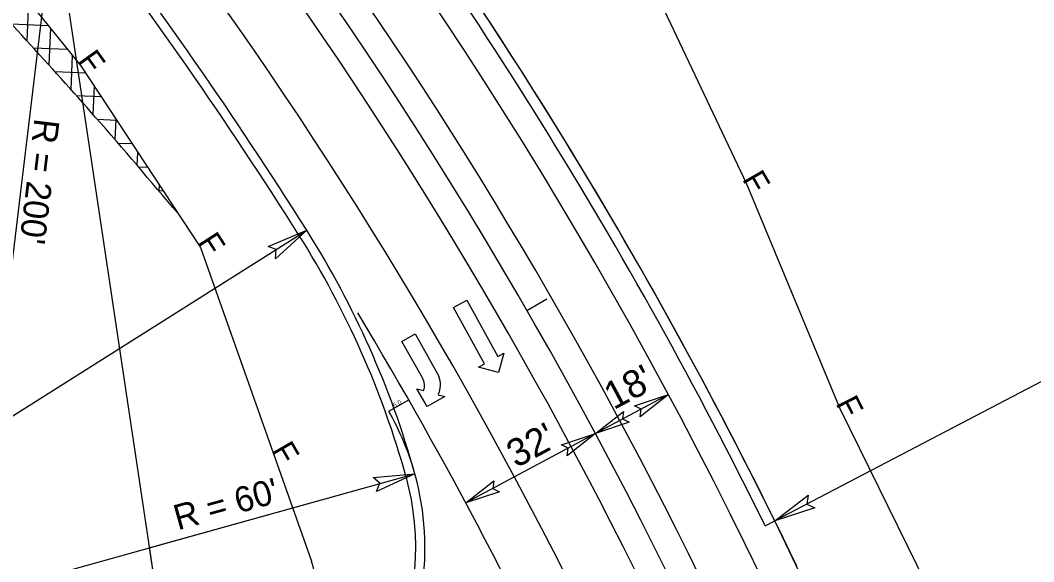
# Model space of a CAD drawing. Extents: x 1702862 to 1704514, y 793768 to 796215.
# Drawn here: x 1703745.4 to 1703965.8, y 794569.2 to 794687 of the extents above; entities that cross this region are included whole.
import ezdxf

# ---------------------------------------------------------------- set-up
doc = ezdxf.new("R2010")
doc.units = 0
for name, color, linetype in [('Prop Conc 2ft 6in Curb and Gutter', 7, 'Continuous'), ('Prop Conc Shoulder Berm Gutter', 7, 'Continuous'), ('Prop Dimension', 7, 'Continuous'), ('Prop Dimension Text', 7, 'Continuous'), ('Prop EOT', 7, 'Continuous'), ('Prop Guardrail', 7, 'Continuous'), ('Prop Horizontal Alignment', 7, 'Continuous'), ('Prop Horizontal Alignment Tick Small', 7, 'Continuous'), ('Prop Lane Arrow CELL', 7, 'Continuous'), ('Prop Lane Lines', 7, 'Continuous'), ('Prop Leader Line Medium', 7, 'Continuous'), ('Prop Paved Shoulder', 7, 'Continuous'), ('Prop Rem of Exist Asph Pvmt', 7, 'Continuous'), ('Prop SS Fill Line', 7, 'Continuous'), ('Prop SS Misc', 7, 'Continuous'), ('Prop SS Transition Line', 7, 'Continuous'), ('Prop Terminator CELL', 7, 'Continuous')]:
    doc.layers.add(name, color=color, linetype=linetype)

msp = doc.modelspace()

# ---------------------------------------------------------------- linework, layer by layer
at = {"layer": 'Prop Conc 2ft 6in Curb and Gutter'}
for centre, radius, start, end in [((1702985.28, 794122.36), 970.46, 32.25438, 42.65517), ((1703638.54, 794534.6), 198, 15.5759, 32.2542), ((1703773.4, 794572.2), 58, 295.8355, 15.5759)]:
    msp.add_arc(centre, radius, start, end, dxfattribs=at)
at = {"layer": 'Prop Conc Shoulder Berm Gutter'}
msp.add_arc((1702988.97, 794124.56), 1026.16, 26.22656, 37.4674, dxfattribs=at)
at = {"layer": 'Prop Dimension'}
for p, q in [((1703752.73, 794710.66), (1703728.81, 794512.1)), ((1703752.73, 794710.66), (1703782.26, 794512.85)), ((1703638.54, 794534.6), (1703807.68, 794641.34)), ((1703825.51, 794601.94), (1703829.85, 794604.42)), ((1703886.34, 794605.58), (1703870.48, 794597.08)), ((1703870.48, 794597.08), (1703842.27, 794581.96)), ((1703638.54, 794534.6), (1703831.2, 794588.31)), ((1703773.4, 794572.2), (1703831.2, 794588.31)), ((1703773.4, 794572.2), (1703782.26, 794512.85))]:
    msp.add_line(p, q, dxfattribs=at)
msp.add_arc((1703773.4, 794572.2), 60, 15.5759, 29.7174, dxfattribs=at)
at = {"layer": 'Prop EOT'}
for centre, radius, start, end in [((1702989.11, 794124.65), 1018, 14.75888, 42.70907), ((1702985.01, 794122.19), 972.78, 32.25419, 42.65174), ((1703638.54, 794534.6), 200, 15.5759, 32.2542), ((1703773.4, 794572.2), 60, 278.4921, 15.5759)]:
    msp.add_arc(centre, radius, start, end, dxfattribs=at)
at = {"layer": 'Prop Guardrail'}
msp.add_arc((1702988.97, 794124.56), 1026.16, 25.61718, 37.4674, dxfattribs=at)
at = {"layer": 'Prop Horizontal Alignment'}
msp.add_arc((1702989.11, 794124.65), 1000, 351.25916, 42.70907, dxfattribs=at)
at = {"layer": 'Prop Horizontal Alignment Tick Small'}
msp.add_line((1703855.57, 794623.89), (1703859.9, 794626.39), dxfattribs=at)
at = {"layer": 'Prop Lane Arrow CELL'}
for p, q in [((1703839.59, 794624.51), (1703842.48, 794626.11)), ((1703846.38, 794612.27), (1703839.59, 794624.51)), ((1703842.48, 794626.11), (1703849.27, 794613.87)), ((1703828.35, 794617.15), (1703831.23, 794618.77)), ((1703831.23, 794618.77), (1703836.41, 794609.58)), ((1703832.85, 794609.18), (1703828.35, 794617.15)), ((1703849.27, 794613.87), (1703850.58, 794614.59)), ((1703850.58, 794614.59), (1703849.39, 794610.33)), ((1703845.07, 794611.54), (1703846.38, 794612.27)), ((1703849.39, 794610.33), (1703845.07, 794611.54)), ((1703833.9, 794602.94), (1703831.65, 794606.83)), ((1703831.65, 794606.83), (1703833.08, 794606.44)), ((1703837.71, 794605.15), (1703833.9, 794602.94)), ((1703836.28, 794605.54), (1703837.71, 794605.15))]:
    msp.add_line(p, q, dxfattribs=at)
for centre, radius, start, end in [((1703830.02, 794607.57), 3.28, 339.7935, 29.4516), ((1703831.52, 794607.73), 5.25, 335.4639, 20.7756)]:
    msp.add_arc(centre, radius, start, end, dxfattribs=at)
at = {"layer": 'Prop Lane Lines'}
for radius, start, end in [(1006, 0.00687, 42.70907), (994, 359.40932, 42.70907), (980, 359.40932, 42.70907), (968, 17.6382, 31.00789)]:
    msp.add_arc((1702989.11, 794124.65), radius, start, end, dxfattribs=at)
at = {"layer": 'Prop Leader Line Medium'}
msp.add_line((1704040.99, 794646.92), (1703909.49, 794578.04), dxfattribs=at)
at = {"layer": 'Prop Paved Shoulder'}
for p in [(1703907.4, 794577.02), (1703914.93, 794566.65)]:
    msp.add_line(p, (1703909.49, 794578.04), dxfattribs=at)
msp.add_arc((1702988.97, 794124.56), 1023.83, 26.22656, 37.4674, dxfattribs=at)
at = {"layer": 'Prop Rem of Exist Asph Pvmt'}
for p, q in [((1703747.15, 794691.23), (1703746.8, 794682.65)), ((1703743.47, 794686.26), (1703751.41, 794685.94)), ((1703751.91, 794685.31), (1703751.6, 794677.4)), ((1703748.26, 794681.06), (1703755.57, 794680.77)), ((1703756.68, 794679.38), (1703756.39, 794672.06)), ((1703752.98, 794675.87), (1703759.5, 794675.61)), ((1703757.61, 794670.68), (1703762.88, 794670.47)), ((1703761.42, 794672.69), (1703761.17, 794666.58)), ((1703762.1, 794665.49), (1703766.27, 794665.33)), ((1703766.14, 794665.53), (1703765.95, 794661)), ((1703766.54, 794660.31), (1703769.65, 794660.19)), ((1703770.85, 794658.36), (1703770.73, 794655.41)), ((1703770.97, 794655.13), (1703773.04, 794655.05)), ((1703775.57, 794651.2), (1703775.52, 794649.83)), ((1703775.41, 794649.95), (1703776.42, 794649.91))]:
    msp.add_line(p, q, dxfattribs=at)
msp.add_spline([(1703779.68, 794644.96), (1703761.75, 794665.91), (1703731.32, 794699.4), (1703700.82, 794732.47), (1703669.4, 794765.36)], degree=3, dxfattribs=at)
at = {"layer": 'Prop SS Fill Line'}
for p, q in [((1703728.84, 794713.99), (1703758.51, 794677.1)), ((1703880.62, 794699.51), (1703903.35, 794651.42)), ((1703758.51, 794677.1), (1703784.55, 794637.56)), ((1703903.35, 794651.42), (1703923.62, 794602.55)), ((1703784.55, 794637.56), (1703808.72, 794569.3)), ((1703923.62, 794602.55), (1703946.81, 794555.47))]:
    msp.add_line(p, q, dxfattribs=at)
at = {"layer": 'Prop SS Transition Line'}
msp.add_arc((1703789.86, 794562.62), 20, 310.3906, 19.4922, dxfattribs=at)
at = {"layer": 'Prop Terminator CELL'}
for points in [[(1703799.25, 794637.83), (1703807.68, 794641.34), (1703800.89, 794635.14), (1703801.01, 794637.11)], [(1703878.98, 794603.13), (1703886.34, 794605.58), (1703880.2, 794600.75), (1703880.42, 794602.41)], [(1703877.84, 794599.53), (1703870.48, 794597.08), (1703876.61, 794601.91), (1703876.39, 794600.25)], [(1703863.11, 794594.63), (1703870.48, 794597.08), (1703864.34, 794592.25), (1703864.56, 794593.91)], [(1703822.1, 794587.49), (1703831.2, 794588.31), (1703822.86, 794584.43), (1703823.56, 794586.28)], [(1703849.64, 794584.42), (1703842.27, 794581.96), (1703848.41, 794586.8), (1703848.19, 794585.14)], [(1703918.18, 794580.87), (1703909.49, 794578.04), (1703916.76, 794583.68), (1703916.48, 794581.72)]]:
    msp.add_lwpolyline(points, close=True, dxfattribs=at)

# ---------------------------------------------------------------- texts
at = {"layer": 'Prop Dimension Text'}
for s, height, rotation, p in [("R = 200'", 5.5, 263.1332, (1703748.46, 794665.83)), ("18'", 6, 28.1924, (1703874.45, 794602.13)), ('5.0', 1, 29.7174, (1703826.76, 794602.65)), ("32'", 6, 28.1924, (1703853.25, 794589.49)), ("R = 60'", 5.5, 15.5759, (1703779.63, 794575.99))]:
    msp.add_text(s, height=height, rotation=rotation, dxfattribs=at).set_placement(p)
at = {"layer": 'Prop SS Misc'}
for rotation, p in [(305.6795, (1703757.69, 794678.25)), (299.95, (1703902.31, 794652.46)), (302.8147, (1703783.78, 794638.75)), (297.0852, (1703922.64, 794603.65)), (299.95, (1703799.89, 794593.45))]:
    msp.add_text('F', height=5, rotation=rotation, dxfattribs=at).set_placement(p)

doc.saveas('drawing.dxf')
